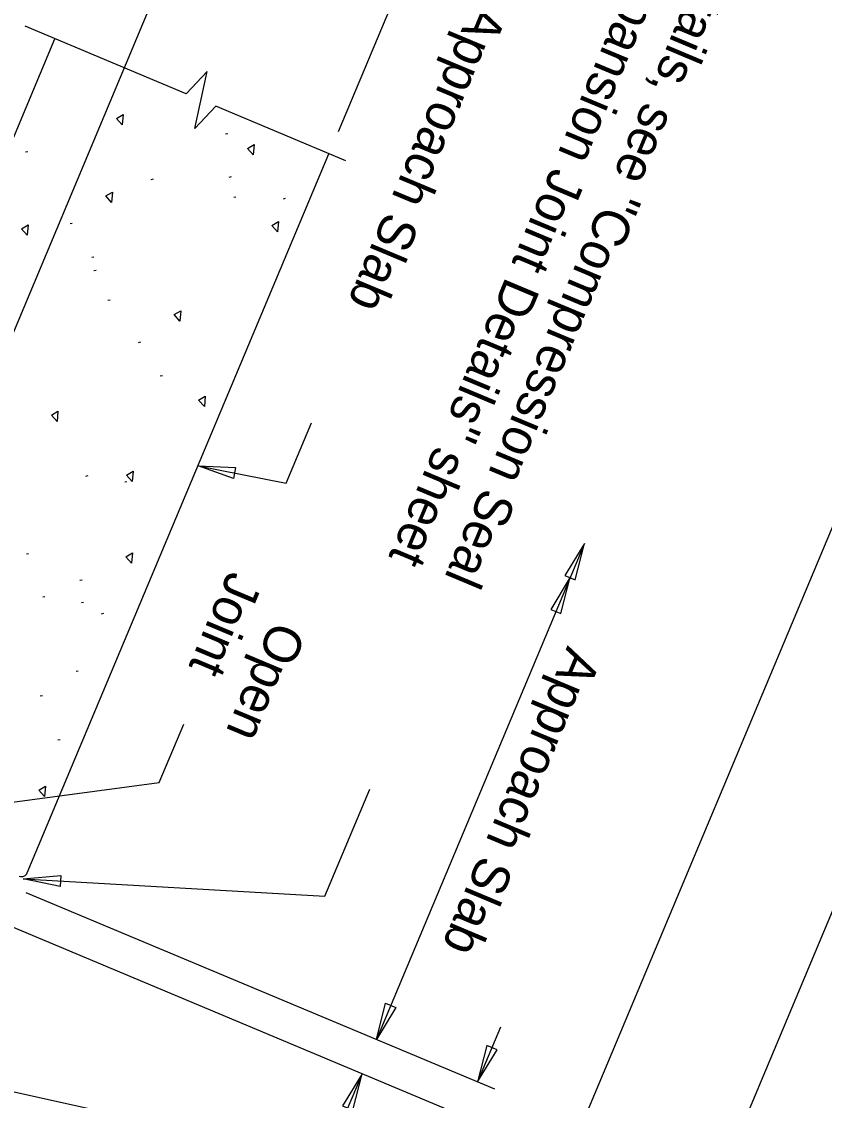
# Model space of a CAD drawing. Extents: x 1968564 to 1968711, y 796599 to 796794.
# Drawn here: x 1968665.06 to 1968675.87, y 796670.24 to 796684.77 of the extents above; entities that cross this region are included whole.
import ezdxf

# ---------------------------------------------------------------- set-up
doc = ezdxf.new("R2010")
doc.units = 0
for name, color, linetype in [('BR_AUTO DIMENSION', 7, 'Continuous'), ('BR_BORDER LINES', 7, 'Continuous'), ('BR_CONCRETE', 7, 'Continuous'), ('BR_DETAILS', 7, 'Continuous'), ('BR_TEXT', 7, 'Continuous'), ('Level 31', 7, 'Continuous')]:
    doc.layers.add(name, color=color, linetype=linetype)

msp = doc.modelspace()

# ---------------------------------------------------------------- linework, layer by layer
at = {"layer": 'BR_AUTO DIMENSION'}
for p, q in [((1968673.24, 796692.621), (1968669.323, 796683.281)), ((1968661.621, 796672.639), (1968666.836, 796685.073)), ((1968668.623, 796678.551), (1968668.964, 796679.363)), ((1968667.438, 796678.787), (1968668.623, 796678.551)), ((1968672.64, 796677.741), (1968669.84, 796671.063)), ((1968666.916, 796674.523), (1968667.246, 796675.309)), ((1968662.785, 796673.971), (1968666.916, 796674.523)), ((1968669.147, 796672.994), (1968669.75, 796674.431)), ((1968665.085, 796673.223), (1968669.147, 796672.994)), ((1968665.119, 796673.043), (1968671.429, 796670.396)), ((1968664.926, 796672.582), (1968671.236, 796669.935)), ((1968671.512, 796671.229), (1968671.203, 796670.491)), ((1968666.9, 796669.924), (1968663.245, 796670.729)), ((1968669.646, 796670.602), (1968666.647, 796663.451))]:
    msp.add_line(p, q, dxfattribs=at)
for points in [[(1968667.914, 796678.615), (1968667.438, 796678.787), (1968667.943, 796678.762)], [(1968672.516, 796677.25), (1968672.64, 796677.741), (1968672.378, 796677.308)], [(1968672.325, 796676.795), (1968672.45, 796677.285), (1968672.187, 796676.853)], [(1968665.58, 796673.12), (1968665.085, 796673.223), (1968665.589, 796673.269)], [(1968670.102, 796671.495), (1968669.84, 796671.063), (1968669.964, 796671.553)], [(1968671.327, 796670.981), (1968671.203, 796670.491), (1968671.466, 796670.923)], [(1968669.522, 796670.112), (1968669.646, 796670.602), (1968669.384, 796670.17)]]:
    msp.add_lwpolyline(points, close=True, dxfattribs=at)
at = {"layer": 'BR_BORDER LINES'}
msp.add_line((1968643.927, 796601.539), (1968696.012, 796725.723), dxfattribs=at)
at = {"layer": 'BR_CONCRETE'}
for p, q in [((1968661.418, 796674.776), (1968665.511, 796684.533)), ((1968665.139, 796673.305), (1968669.2, 796682.986))]:
    msp.add_line(p, q, dxfattribs=at)
msp.add_arc((1968665.062, 796673.338), 0.0833, 247.246, 337.2565, dxfattribs=at)
at = {"layer": 'BR_DETAILS'}
for p, q in [((1968667.277, 796683.793), (1968665.108, 796684.702)), ((1968669.43, 796682.89), (1968667.677, 796683.625)), ((1968667.809, 796683.256), (1968667.838, 796683.261)), ((1968665.115, 796683.012), (1968665.144, 796683.018)), ((1968666.808, 796682.641), (1968666.837, 796682.647)), ((1968667.857, 796682.673), (1968667.887, 796682.679)), ((1968667.919, 796682.402), (1968667.948, 796682.408)), ((1968668.588, 796682.38), (1968668.617, 796682.386)), ((1968665.714, 796682.045), (1968665.743, 796682.051)), ((1968666.006, 796681.594), (1968666.035, 796681.6)), ((1968666.037, 796681.413), (1968666.067, 796681.419)), ((1968666.225, 796681.016), (1968666.254, 796681.021)), ((1968666.636, 796680.446), (1968666.666, 796680.452)), ((1968666.929, 796679.995), (1968666.958, 796680.001)), ((1968665.929, 796678.647), (1968665.958, 796678.653)), ((1968666.451, 796678.57), (1968666.48, 796678.576)), ((1968665.127, 796677.6), (1968665.157, 796677.606)), ((1968665.848, 796677.245), (1968665.877, 796677.251)), ((1968665.346, 796677.021), (1968665.375, 796677.027)), ((1968665.868, 796676.944), (1968665.897, 796676.95)), ((1968666.14, 796676.794), (1968666.17, 796676.8)), ((1968665.796, 796676.021), (1968665.826, 796676.026)), ((1968665.314, 796675.688), (1968665.344, 796675.693)), ((1968665.551, 796675.095), (1968665.58, 796675.101))]:
    msp.add_line(p, q, dxfattribs=at)
for points in [[(1968667.677, 796683.625), (1968667.394, 796683.325), (1968667.559, 796684.093), (1968667.277, 796683.793)], [(1968666.418, 796683.374), (1968666.341, 796683.46), (1968666.431, 796683.513), (1968666.418, 796683.374)], [(1968668.18, 796682.971), (1968668.103, 796683.057), (1968668.193, 796683.11), (1968668.18, 796682.971)], [(1968666.271, 796682.332), (1968666.195, 796682.418), (1968666.284, 796682.471), (1968666.271, 796682.332)], [(1968665.139, 796681.89), (1968665.062, 796681.976), (1968665.152, 796682.029), (1968665.139, 796681.89)], [(1968668.507, 796681.934), (1968668.43, 796682.021), (1968668.52, 796682.073), (1968668.507, 796681.934)], [(1968667.194, 796680.733), (1968667.117, 796680.82), (1968667.207, 796680.872), (1968667.194, 796680.733)], [(1968667.523, 796679.583), (1968667.446, 796679.669), (1968667.536, 796679.722), (1968667.523, 796679.583)], [(1968665.539, 796679.38), (1968665.463, 796679.466), (1968665.552, 796679.519), (1968665.539, 796679.38)], [(1968666.552, 796678.574), (1968666.476, 796678.66), (1968666.565, 796678.713), (1968666.552, 796678.574)], [(1968666.544, 796677.474), (1968666.467, 796677.56), (1968666.557, 796677.613), (1968666.544, 796677.474)], [(1968665.371, 796674.333), (1968665.294, 796674.42), (1968665.384, 796674.472), (1968665.371, 796674.333)]]:
    msp.add_lwpolyline(points, dxfattribs=at)
at = {"layer": 'Level 31'}
msp.add_lwpolyline([(1968619.541, 796765.748), (1968563.846, 796632.955), (1968644.997, 796598.919), (1968700.693, 796731.712)], close=True, dxfattribs=at)

# ---------------------------------------------------------------- texts
at = {"layer": 'BR_TEXT'}
for s, height, p in [('For Details, see "Compression Seal ', 0.49995, (1968674.837, 796687.023)), ('Top of Approach Slab', 0.49995, (1968671.95, 796686.956)), ('Expansion Joint Details" sheet', 0.49995, (1968673.485, 796685.868)), ('Joint', 0.4999, (1968667.855, 796677.388)), ('Open', 0.4999, (1968668.441, 796676.718)), ('Approach Slab', 0.49995, (1968672.415, 796676.373))]:
    msp.add_text(s, height=height, rotation=247.246, dxfattribs=at).set_placement(p)

doc.saveas('drawing.dxf')
